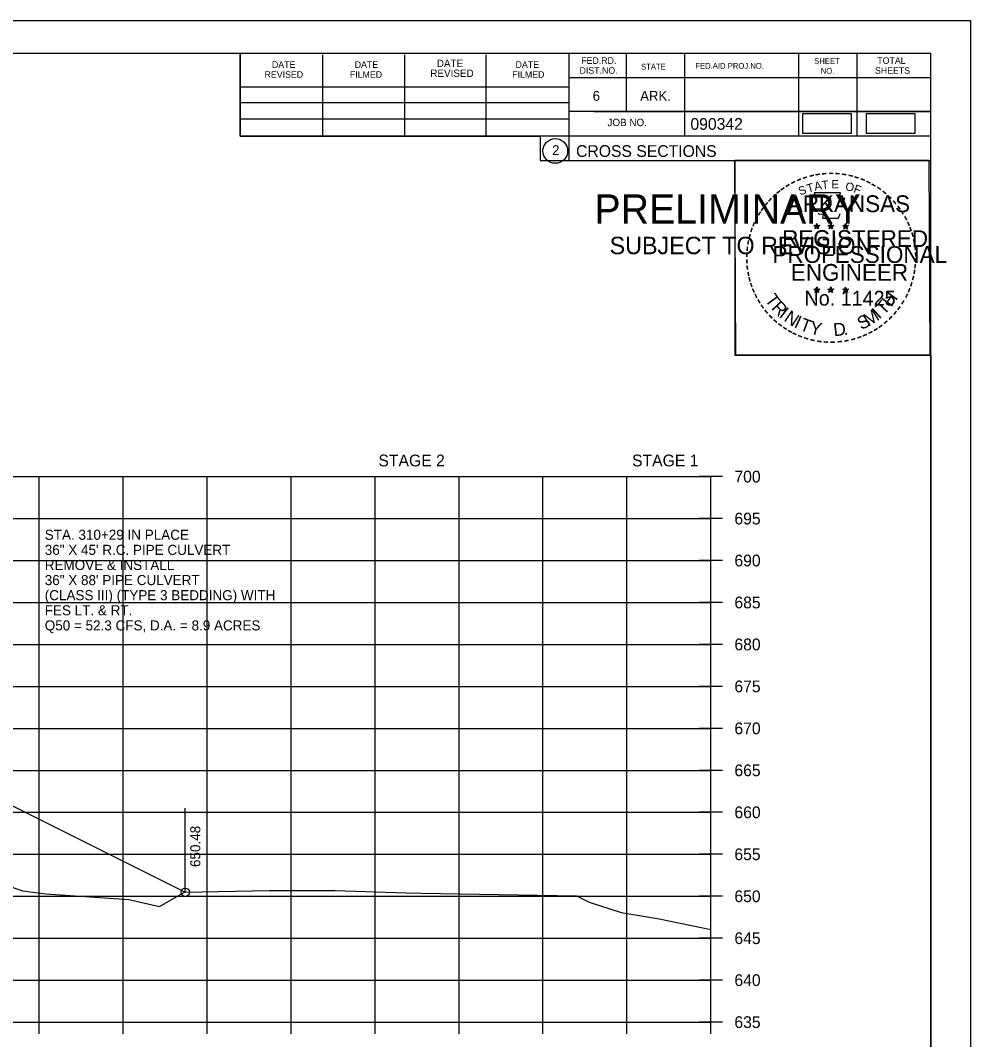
# Model space of a CAD drawing. Extents: x 1370515 to 1370849, y 383299 to 386073.
# Drawn here: x 1370735.6 to 1370848.7, y 384884.7 to 385006.1 of the extents above; entities that cross this region are included whole.
import ezdxf

# ---------------------------------------------------------------- set-up
doc = ezdxf.new("R2010")
doc.units = 0
for name, color, linetype in [('R_Axis', 7, 'Continuous'), ('R_Axis Annot', 7, 'Continuous'), ('R_Border', 7, 'Continuous'), ('R_Border PE', 7, 'Continuous'), ('R_Border Prem', 7, 'Continuous'), ('R_Detour', 7, 'Continuous'), ('R_Exist Surface', 7, 'Continuous'), ('R_Fin Surface', 7, 'Continuous'), ('R_Grid', 7, 'Continuous'), ('R_No Plot', 7, 'Continuous'), ('R_Water', 7, 'Continuous'), ('R_Xsect Elev', 7, 'Continuous')]:
    doc.layers.add(name, color=color, linetype=linetype)

msp = doc.modelspace()

# ---------------------------------------------------------------- linework, layer by layer
at = {"layer": 'R_Axis'}
for p, q in [((1370819.2, 384951.77), (1370816.4, 384951.77)), ((1370817.8, 384886.77), (1370817.8, 384951.77)), ((1370819.2, 384946.77), (1370816.4, 384946.77)), ((1370819.2, 384941.77), (1370816.4, 384941.77)), ((1370819.2, 384936.77), (1370816.4, 384936.77)), ((1370819.2, 384931.77), (1370816.4, 384931.77)), ((1370819.2, 384926.77), (1370816.4, 384926.77)), ((1370819.2, 384921.77), (1370816.4, 384921.77)), ((1370819.2, 384916.77), (1370816.4, 384916.77)), ((1370819.2, 384911.77), (1370816.4, 384911.77)), ((1370819.2, 384906.77), (1370816.4, 384906.77)), ((1370819.2, 384901.77), (1370816.4, 384901.77)), ((1370819.2, 384896.77), (1370816.4, 384896.77)), ((1370819.2, 384891.77), (1370816.4, 384891.77)), ((1370737.8, 384885.37), (1370737.8, 384888.17)), ((1370747.8, 384885.37), (1370747.8, 384888.17)), ((1370757.8, 384885.37), (1370757.8, 384888.17)), ((1370767.8, 384885.37), (1370767.8, 384888.17)), ((1370777.8, 384885.37), (1370777.8, 384888.17)), ((1370787.8, 384885.37), (1370787.8, 384888.17)), ((1370797.8, 384885.37), (1370797.8, 384888.17)), ((1370807.8, 384885.37), (1370807.8, 384888.17)), ((1370817.8, 384885.37), (1370817.8, 384888.17)), ((1370537.8, 384886.77), (1370817.8, 384886.77)), ((1370819.2, 384886.77), (1370816.4, 384886.77))]:
    msp.add_line(p, q, dxfattribs=at)
at = {"layer": 'R_Border'}
for p, q in [((1370527.8, 385002.23), (1370843.98, 385002.23)), ((1370761.72, 384992.35), (1370761.72, 385002.23)), ((1370771.58, 384992.35), (1370771.58, 385002.03)), ((1370781.34, 384992.35), (1370781.34, 385002.03)), ((1370791.02, 384992.35), (1370791.02, 385002.03)), ((1370800.88, 385002.23), (1370800.88, 384989.43)), ((1370807.72, 385002.23), (1370807.72, 384995.29)), ((1370814.66, 385002.23), (1370814.66, 384992.35)), ((1370828.24, 385002.23), (1370828.24, 384992.35)), ((1370835.18, 385002.23), (1370835.18, 384992.35)), ((1370843.98, 384796.77), (1370843.98, 385002.23)), ((1370843.98, 384999.29), (1370800.88, 384999.29)), ((1370843.98, 384999.31), (1370843.98, 384999.31)), ((1370761.72, 384998.21), (1370800.88, 384998.21)), ((1370761.72, 384996.35), (1370800.88, 384996.35)), ((1370843.98, 384995.29), (1370800.88, 384995.29)), ((1370803.84, 384995.29), (1370843.98, 384995.29)), ((1370761.72, 384992.35), (1370761.72, 384994.41)), ((1370761.72, 384994.41), (1370800.88, 384994.41)), ((1370843.98, 384992.35), (1370761.72, 384992.35)), ((1370800.88, 384989.43), (1370843.98, 384989.43))]:
    msp.add_line(p, q, dxfattribs=at)
msp.add_circle((1370799.27, 384990.57), 1.47, dxfattribs=at)
at = {"layer": 'R_Border PE'}
for p, q in [((1370830.42, 384981.94), (1370830.37, 384981.69)), ((1370830.42, 384981.58), (1370830.42, 384981.94)), ((1370830.42, 384981.94), (1370830.46, 384981.69)), ((1370832.09, 384981.94), (1370832.04, 384981.69)), ((1370832.09, 384981.58), (1370832.09, 384981.94)), ((1370832.09, 384981.94), (1370832.13, 384981.69)), ((1370833.85, 384981.93), (1370833.81, 384981.68)), ((1370833.85, 384981.57), (1370833.85, 384981.93)), ((1370833.85, 384981.93), (1370833.9, 384981.68)), ((1370830.07, 384981.69), (1370830.42, 384981.58)), ((1370830.07, 384981.69), (1370830.32, 384981.64)), ((1370830.07, 384981.69), (1370830.3, 384981.57)), ((1370830.2, 384981.28), (1370830.42, 384981.58)), ((1370830.2, 384981.28), (1370830.33, 384981.53)), ((1370830.2, 384981.28), (1370830.41, 384981.5)), ((1370830.63, 384981.28), (1370830.41, 384981.5)), ((1370830.76, 384981.69), (1370830.42, 384981.58)), ((1370830.63, 384981.28), (1370830.42, 384981.58)), ((1370830.76, 384981.69), (1370830.48, 384981.64)), ((1370830.63, 384981.28), (1370830.49, 384981.57)), ((1370830.76, 384981.69), (1370830.56, 384981.59)), ((1370831.74, 384981.69), (1370832.09, 384981.58)), ((1370831.74, 384981.69), (1370831.99, 384981.64)), ((1370831.74, 384981.69), (1370831.97, 384981.57)), ((1370831.87, 384981.28), (1370832.09, 384981.58)), ((1370831.87, 384981.28), (1370832, 384981.53)), ((1370831.87, 384981.28), (1370832.08, 384981.5)), ((1370832.3, 384981.28), (1370832.08, 384981.5)), ((1370832.43, 384981.69), (1370832.09, 384981.58)), ((1370832.3, 384981.28), (1370832.09, 384981.58)), ((1370832.43, 384981.69), (1370832.15, 384981.64)), ((1370832.3, 384981.28), (1370832.16, 384981.57)), ((1370832.43, 384981.69), (1370832.23, 384981.59)), ((1370833.5, 384981.68), (1370833.85, 384981.57)), ((1370833.5, 384981.68), (1370833.75, 384981.63)), ((1370833.5, 384981.68), (1370833.74, 384981.56)), ((1370833.63, 384981.27), (1370833.85, 384981.57)), ((1370833.63, 384981.27), (1370833.76, 384981.51)), ((1370833.63, 384981.27), (1370833.85, 384981.49)), ((1370834.2, 384981.68), (1370833.85, 384981.57)), ((1370834.06, 384981.27), (1370833.85, 384981.57)), ((1370834.06, 384981.27), (1370833.85, 384981.48)), ((1370834.2, 384981.68), (1370833.91, 384981.63)), ((1370834.06, 384981.27), (1370833.93, 384981.56)), ((1370834.2, 384981.68), (1370833.99, 384981.58)), ((1370830.06, 384974.12), (1370830.41, 384974.01)), ((1370830.06, 384974.12), (1370830.32, 384974.07)), ((1370830.06, 384974.12), (1370830.3, 384973.99)), ((1370830.2, 384973.71), (1370830.41, 384974.01)), ((1370830.2, 384973.71), (1370830.32, 384973.95)), ((1370830.2, 384973.71), (1370830.41, 384973.93)), ((1370830.41, 384974.37), (1370830.37, 384974.12)), ((1370830.41, 384974.01), (1370830.41, 384974.37)), ((1370830.41, 384974.37), (1370830.46, 384974.12)), ((1370830.76, 384974.12), (1370830.41, 384974.01)), ((1370830.62, 384973.71), (1370830.41, 384974.01)), ((1370830.62, 384973.71), (1370830.41, 384973.92)), ((1370830.76, 384974.12), (1370830.47, 384974.07)), ((1370830.62, 384973.71), (1370830.49, 384974)), ((1370830.76, 384974.12), (1370830.55, 384974.01)), ((1370831.73, 384974.12), (1370832.08, 384974.01)), ((1370831.73, 384974.12), (1370831.98, 384974.07)), ((1370831.73, 384974.12), (1370831.97, 384973.99)), ((1370831.86, 384973.71), (1370832.08, 384974.01)), ((1370831.86, 384973.71), (1370831.99, 384973.95)), ((1370831.86, 384973.71), (1370832.08, 384973.93)), ((1370832.08, 384974.37), (1370832.04, 384974.12)), ((1370832.08, 384974.01), (1370832.08, 384974.37)), ((1370832.08, 384974.37), (1370832.13, 384974.12)), ((1370832.43, 384974.12), (1370832.08, 384974.01)), ((1370832.29, 384973.71), (1370832.08, 384974.01)), ((1370832.29, 384973.71), (1370832.08, 384973.92)), ((1370832.43, 384974.12), (1370832.14, 384974.07)), ((1370832.29, 384973.71), (1370832.16, 384974)), ((1370832.43, 384974.12), (1370832.22, 384974.01)), ((1370833.5, 384974.11), (1370833.85, 384974)), ((1370833.5, 384974.11), (1370833.75, 384974.06)), ((1370833.5, 384974.11), (1370833.74, 384973.98)), ((1370833.63, 384973.7), (1370833.85, 384974)), ((1370833.63, 384973.7), (1370833.76, 384973.94)), ((1370833.63, 384973.7), (1370833.85, 384973.92)), ((1370833.85, 384974.36), (1370833.81, 384974.11)), ((1370833.85, 384974), (1370833.85, 384974.36)), ((1370833.85, 384974.36), (1370833.9, 384974.11)), ((1370834.19, 384974.11), (1370833.85, 384974)), ((1370834.06, 384973.7), (1370833.85, 384974)), ((1370834.06, 384973.7), (1370833.85, 384973.91)), ((1370834.19, 384974.11), (1370833.91, 384974.06)), ((1370834.06, 384973.7), (1370833.92, 384973.99)), ((1370834.19, 384974.11), (1370833.99, 384974))]:
    msp.add_line(p, q, dxfattribs=at)
for points in [[(1370830.11, 384985.57), (1370830.38, 384984.74)], [(1370833.62, 384984.65), (1370833.76, 384984.93), (1370833.08, 384984.91), (1370833.22, 384985.57), (1370830.11, 384985.57)], [(1370830.6, 384983.14), (1370830.6, 384983.06), (1370831.16, 384983.04), (1370831.11, 384982.57), (1370832.98, 384982.57), (1370833.18, 384983.1)], [(1370830.42, 384981.94), (1370830.63, 384981.28), (1370830.07, 384981.69), (1370830.76, 384981.69), (1370830.2, 384981.28), (1370830.42, 384981.94)], [(1370832.09, 384981.94), (1370832.3, 384981.28), (1370831.74, 384981.69), (1370832.43, 384981.69), (1370831.87, 384981.28), (1370832.09, 384981.94)], [(1370833.85, 384981.93), (1370834.06, 384981.27), (1370833.5, 384981.68), (1370834.2, 384981.68), (1370833.63, 384981.27), (1370833.85, 384981.93)], [(1370830.41, 384974.37), (1370830.62, 384973.71), (1370830.06, 384974.12), (1370830.76, 384974.12), (1370830.2, 384973.71), (1370830.41, 384974.37)], [(1370832.08, 384974.37), (1370832.29, 384973.71), (1370831.73, 384974.12), (1370832.43, 384974.12), (1370831.86, 384973.71), (1370832.08, 384974.37)], [(1370833.85, 384974.36), (1370834.06, 384973.7), (1370833.5, 384974.11), (1370834.19, 384974.11), (1370833.63, 384973.7), (1370833.85, 384974.36)]]:
    msp.add_lwpolyline(points, dxfattribs=at)
for centre, radius in [((1370830.41, 384981.58), 0.172), ((1370830.41, 384981.58), 0.145), ((1370830.41, 384981.58), 0.116), ((1370830.41, 384981.58), 0.0991), ((1370830.41, 384981.58), 0.0747), ((1370830.41, 384981.58), 0.0495), ((1370830.41, 384981.58), 0.0296), ((1370832.08, 384981.58), 0.172), ((1370832.08, 384981.58), 0.145), ((1370832.08, 384981.58), 0.116), ((1370832.08, 384981.58), 0.0991), ((1370832.08, 384981.58), 0.0747), ((1370832.08, 384981.58), 0.0495), ((1370832.08, 384981.58), 0.0296), ((1370833.85, 384981.57), 0.172), ((1370833.85, 384981.57), 0.145), ((1370833.85, 384981.57), 0.116), ((1370833.85, 384981.57), 0.0991), ((1370833.85, 384981.57), 0.0747), ((1370833.85, 384981.57), 0.0495), ((1370833.85, 384981.57), 0.0296), ((1370830.41, 384974.01), 0.172), ((1370830.41, 384974.01), 0.145), ((1370830.41, 384974.01), 0.116), ((1370830.41, 384974.01), 0.0991), ((1370830.41, 384974.01), 0.0747), ((1370830.41, 384974.01), 0.0495), ((1370830.41, 384974.01), 0.0296), ((1370832.08, 384974.01), 0.172), ((1370832.08, 384974.01), 0.145), ((1370832.08, 384974.01), 0.116), ((1370832.08, 384974.01), 0.0991), ((1370832.08, 384974.01), 0.0747), ((1370832.08, 384974.01), 0.0495), ((1370832.08, 384974.01), 0.0296), ((1370833.85, 384974), 0.172), ((1370833.85, 384974), 0.145), ((1370833.85, 384974), 0.116), ((1370833.85, 384974), 0.0991), ((1370833.85, 384974), 0.0747), ((1370833.85, 384974), 0.0495), ((1370833.85, 384974), 0.0296)]:
    msp.add_circle(centre, radius, dxfattribs=at)
at = {"layer": 'R_Detour'}
for points in [[(1370828.7, 384992.69), (1370834.53, 384992.69), (1370834.53, 384995), (1370828.7, 384995)], [(1370836.3, 384992.69), (1370842.14, 384992.69), (1370842.14, 384995), (1370836.3, 384995)]]:
    msp.add_lwpolyline(points, close=True, dxfattribs=at)
at = {"layer": 'R_Exist Surface'}
msp.add_lwpolyline([(1370734.44, 384902.89), (1370735.82, 384902.41), (1370738.57, 384902.04), (1370748.48, 384901.37), (1370752.12, 384900.55), (1370755.09, 384902.24), (1370755.18, 384902.25), (1370765.19, 384902.47), (1370773.06, 384902.46), (1370781.52, 384902.18), (1370783.3, 384902.14), (1370801.8, 384901.8), (1370803.3, 384901.06), (1370807.11, 384899.83), (1370811.64, 384899.06), (1370817.8, 384897.82)], dxfattribs=at)
at = {"layer": 'R_Fin Surface'}
msp.add_lwpolyline([(1370588.17, 384925.44), (1370626.49, 384923.33), (1370651.8, 384931.77), (1370657.8, 384933.27), (1370665.8, 384932.51), (1370677.8, 384931.36), (1370689.8, 384930.21), (1370697.8, 384929.45), (1370703.8, 384927.95), (1370708.72, 384925.49), (1370755.19, 384902.25)], dxfattribs=at)
at = {"layer": 'R_Grid'}
for p, q in [((1370537.8, 384951.77), (1370817.8, 384951.77)), ((1370737.8, 384886.77), (1370737.8, 384951.77)), ((1370747.8, 384886.77), (1370747.8, 384951.77)), ((1370757.8, 384886.77), (1370757.8, 384951.77)), ((1370767.8, 384886.77), (1370767.8, 384951.77)), ((1370777.8, 384886.77), (1370777.8, 384951.77)), ((1370787.8, 384886.77), (1370787.8, 384951.77)), ((1370797.8, 384886.77), (1370797.8, 384951.77)), ((1370807.8, 384886.77), (1370807.8, 384951.77)), ((1370817.8, 384886.77), (1370817.8, 384951.77)), ((1370537.8, 384946.77), (1370817.8, 384946.77)), ((1370537.8, 384941.77), (1370817.8, 384941.77)), ((1370537.8, 384936.77), (1370817.8, 384936.77)), ((1370537.8, 384931.77), (1370817.8, 384931.77)), ((1370537.8, 384926.77), (1370817.8, 384926.77)), ((1370537.8, 384921.77), (1370817.8, 384921.77)), ((1370537.8, 384916.77), (1370817.8, 384916.77)), ((1370537.8, 384911.77), (1370817.8, 384911.77)), ((1370537.8, 384906.77), (1370817.8, 384906.77)), ((1370537.8, 384901.77), (1370817.8, 384901.77)), ((1370537.8, 384896.77), (1370817.8, 384896.77)), ((1370537.8, 384891.77), (1370817.8, 384891.77)), ((1370537.8, 384886.77), (1370817.8, 384886.77))]:
    msp.add_line(p, q, dxfattribs=at)
at = {"layer": 'R_No Plot'}
for p, q in [((1370515.4, 385006.13), (1370848.73, 385006.13)), ((1370820.02, 384966.98), (1370820.02, 384966.98))]:
    msp.add_line(p, q, dxfattribs=at)
for points in [[(1370515.39, 385006.13), (1370848.73, 385006.13), (1370848.73, 384792.79), (1370515.39, 384792.79)], [(1370761.72, 385002.23), (1370761.72, 384992.35), (1370797.45, 384992.35), (1370797.45, 384989.43), (1370820.65, 384989.43), (1370820.65, 384966.22), (1370843.98, 384966.22), (1370843.98, 384796.77), (1370527.8, 384796.77), (1370527.8, 385002.23)], [(1370820.65, 384989.47), (1370843.75, 384989.47), (1370843.87, 384966.22), (1370820.77, 384966.22)]]:
    msp.add_lwpolyline(points, close=True, dxfattribs=at)
msp.add_circle((1370755.19, 384902.25), 0.5, dxfattribs=at)
at = {"layer": 'R_Xsect Elev'}
msp.add_line((1370755.19, 384902.25), (1370755.19, 384912.25), dxfattribs=at)

# ---------------------------------------------------------------- texts
at = {"layer": 'R_Axis Annot'}
for s, p in [('STAGE 2', (1370778.2, 384952.99)), ('STAGE 1', (1370808.41, 384952.99)), ('700', (1370820.6, 384951.07)), ('695', (1370820.6, 384946.07)), ('690', (1370820.6, 384941.07)), ('685', (1370820.6, 384936.07)), ('680', (1370820.6, 384931.07)), ('675', (1370820.6, 384926.07)), ('670', (1370820.6, 384921.07)), ('665', (1370820.6, 384916.07)), ('660', (1370820.6, 384911.07)), ('655', (1370820.6, 384906.07)), ('650', (1370820.6, 384901.07)), ('645', (1370820.6, 384896.07)), ('640', (1370820.6, 384891.07)), ('635', (1370820.6, 384886.07))]:
    msp.add_text(s, height=1.4, dxfattribs=at).set_placement(p)
at = {"layer": 'R_Border'}
for s, height, p in [('DATE', 0.879, (1370785.16, 385000.57)), ('FED.RD.', 0.782, (1370802.36, 385000.95)), ('SHEET', 0.684, (1370830.1, 385000.95)), ('TOTAL', 0.782, (1370837.62, 385000.95)), ('REVISED', 0.782, (1370764.64, 384999.29)), ('DATE', 0.782, (1370765.52, 385000.47)), ('FILMED', 0.782, (1370774.8, 384999.29)), ('DATE', 0.782, (1370775.38, 385000.47)), ('REVISED', 0.879, (1370784.38, 384999.39)), ('FILMED', 0.782, (1370794.14, 384999.29)), ('DATE', 0.782, (1370794.54, 385000.47)), ('DIST.NO.', 0.782, (1370802.16, 384999.77)), ('STATE', 0.684, (1370809.48, 385000.27)), ('FED.AID PROJ.NO.', 0.684, (1370815.94, 385000.37)), ('NO.', 0.684, (1370830.88, 384999.77)), ('SHEETS', 0.782, (1370837.34, 384999.77)), ('6', 1.17, (1370803.72, 384996.55)), ('ARK.', 1.172, (1370809.38, 384996.55)), ('JOB NO.', 0.879, (1370805.48, 384993.53)), ('090342', 1.4, (1370815.36, 384993.09)), ('2', 1.17, (1370798.89, 384990.08)), ('CROSS SECTIONS', 1.4, (1370801.74, 384989.86))]:
    msp.add_text(s, height=height, rotation=360, dxfattribs=at).set_placement(p)
at = {"layer": 'R_Border PE'}
for s, height, rotation, p in [('-', 1.6, 5.8968, (1370831.01, 384987.21)), ('-', 1.6, 0.1862, (1370831.78, 384987.28)), ('-', 1.6, 357.743, (1370832.51, 384987.27)), ('-', 1.6, 28.7918, (1370827.59, 384986.11)), ('-', 1.6, 24.3072, (1370828.22, 384986.43)), ('-', 1.6, 19.1761, (1370828.86, 384986.69)), ('T', 1, 16.4036, (1370829.38, 384985.58)), ('-', 1.6, 13.6301, (1370829.61, 384986.94)), ('A', 1, 11.2132, (1370830.2, 384985.83)), ('-', 1.6, 10.2193, (1370830.28, 384987.1)), ('T', 1, 6.0228, (1370831.05, 384985.99)), ('E', 1, 0.8323, (1370832.16, 384986.1)), ('-', 1.6, 352.1617, (1370833.25, 384987.21)), ('O', 1, 350.4515, (1370833.76, 384985.89)), ('-', 1.6, 347.2049, (1370833.97, 384987.1)), ('-', 1.6, 342.3362, (1370834.61, 384986.94)), ('-', 1.6, 337.8551, (1370835.34, 384986.72)), ('-', 1.6, 334.1211, (1370835.97, 384986.45)), ('-', 1.6, 329.6409, (1370836.55, 384986.16)), ('-', 1.6, 42.9622, (1370825.5, 384984.55)), ('-', 1.6, 38.9507, (1370825.94, 384984.97)), ('-', 1.6, 36.2317, (1370826.41, 384985.34)), ('-', 1.6, 34.0636, (1370826.99, 384985.74)), ('S', 1, 21.594, (1370828.46, 384985.25)), ('F', 1, 340.0707, (1370834.71, 384985.67)), ('-', 1.6, 325.8627, (1370837.19, 384985.8)), ('-', 1.6, 320.5297, (1370837.8, 384985.38)), ('-', 1.6, 50.6142, (1370824.65, 384983.58)), ('-', 1.6, 48.423, (1370825.06, 384984.07)), ('ARKANSAS', 2, 360, (1370826.96, 384983.28)), ('-', 1.6, 315.5786, (1370838.4, 384984.89)), ('-', 1.6, 309.8797, (1370838.97, 384984.34)), ('-', 1.6, 58.0706, (1370823.92, 384982.49)), ('-', 1.6, 54.2325, (1370824.24, 384983.02)), ('-', 1.6, 306.6522, (1370839.5, 384983.74)), ('-', 1.4, 303.6753, (1370839.98, 384983.17)), ('-', 1.6, 67.7743, (1370823.34, 384981.27)), ('-', 1.6, 62.8713, (1370823.6, 384981.88)), ('-', 1.6, 299.6684, (1370840.3, 384982.56)), ('-', 1.6, 294.6628, (1370840.63, 384981.95)), ('-', 1.6, 75.461, (1370822.93, 384979.92)), ('-', 1.6, 72.3945, (1370823.12, 384980.64)), ('REGISTERED', 2, 360, (1370826.28, 384979.13)), ('DWB', 0.01, 360, (1370830.4, 384981.57)), ('DWB', 0.01, 360, (1370832.07, 384981.57)), ('DWB', 0.01, 360, (1370833.84, 384981.56)), ('-', 1.6, 290.5728, (1370840.88, 384981.37)), ('-', 1.6, 285.1233, (1370841.12, 384980.79)), ('-', 1.6, 81.2013, (1370822.8, 384979.21)), ('-', 1.6, 280.5493, (1370841.32, 384980.05)), ('-', 1.6, 89.0622, (1370822.69, 384977.82)), ('-', 1.6, 85.1863, (1370822.72, 384978.52)), ('PROFESSIONAL', 2, 360, (1370825.13, 384977.23)), ('-', 1.6, 276.5962, (1370841.48, 384979.28)), ('-', 1.6, 274.3301, (1370841.54, 384978.56)), ('-', 1.6, 94.1959, (1370822.73, 384977.09)), ('ENGINEER', 2, 360, (1370827.32, 384975.1)), ('-', 1.6, 263.5172, (1370841.55, 384977.26)), ('-', 1.6, 269.9407, (1370841.57, 384977.93)), ('-', 1.6, 98.9479, (1370822.8, 384976.42)), ('-', 1.6, 101.7149, (1370822.94, 384975.69)), ('-', 1.6, 260.9953, (1370841.48, 384976.61)), ('-', 1.6, 105.4578, (1370823.1, 384975.1)), ('-', 1.6, 109.0874, (1370823.31, 384974.47)), ('-', 1.6, 252.8681, (1370841.19, 384975.21)), ('-', 1.6, 255.7626, (1370841.37, 384975.93)), ('-', 1.6, 114.0643, (1370823.57, 384973.87)), ('-', 1.6, 115.7288, (1370823.87, 384973.25)), ('T', 1.54, 306.0406, (1370824.17, 384972.84)), ('No. 11425', 1.757, 360, (1370828.95, 384972.15)), ('DWB', 0.01, 360, (1370830.4, 384974)), ('DWB', 0.01, 360, (1370832.07, 384974)), ('DWB', 0.01, 360, (1370833.83, 384973.99)), ('H', 1.54, 54.6088, (1370839.29, 384971.88)), ('-', 1.6, 244.6197, (1370840.71, 384973.91)), ('-', 1.6, 247.8887, (1370840.97, 384974.54)), ('-', 1.6, 120.4471, (1370824.23, 384972.67)), ('-', 1.6, 125.8934, (1370824.63, 384972.1)), ('R', 1.54, 314.005, (1370824.93, 384971.8)), ('T', 1.54, 46.6444, (1370838.4, 384970.94)), ('-', 1.6, 239.0712, (1370840.31, 384973.16)), ('-', 1.6, 130.7181, (1370825.09, 384971.55)), ('-', 1.6, 134.2238, (1370825.61, 384971.01)), ('I', 1.54, 321.9694, (1370825.83, 384970.86)), ('N', 1.54, 326.5002, (1370826.4, 384970.39)), ('I', 1.54, 335.3603, (1370827.61, 384969.61)), ('S', 1.54, 26.9312, (1370835.72, 384969.21)), ('M', 1.54, 32.6563, (1370836.56, 384969.61)), ('I', 1.54, 42.1136, (1370837.84, 384970.46)), ('-', 1.6, 225.7653, (1370839, 384971.37)), ('-', 1.6, 231.2538, (1370839.48, 384971.94)), ('-', 1.6, 233.8452, (1370839.91, 384972.5)), ('-', 1.6, 138.9338, (1370826.14, 384970.54)), ('-', 1.6, 144.6463, (1370826.69, 384970.14)), ('T', 1.54, 339.8912, (1370828.27, 384969.28)), ('Y', 1.54, 347.8556, (1370829.49, 384968.83)), ('D', 1.54, 6.3969, (1370832.47, 384968.48)), ('-', 1.6, 215.7363, (1370837.93, 384970.39)), ('-', 1.6, 221.0851, (1370838.48, 384970.87)), ('-', 1.6, 148.0898, (1370827.25, 384969.77)), ('-', 1.6, 151.5704, (1370827.83, 384969.44)), ('-', 1.6, 154.6002, (1370828.35, 384969.19)), ('-', 1.6, 158.5612, (1370828.98, 384968.94)), ('.', 1.54, 13.7642, (1370833.66, 384968.6)), ('-', 1.6, 200.7184, (1370835.6, 384969.07)), ('-', 1.6, 204.2516, (1370836.21, 384969.34)), ('-', 1.6, 207.3568, (1370836.84, 384969.66)), ('-', 1.6, 212.2491, (1370837.4, 384970.01)), ('-', 1.6, 162.7983, (1370829.67, 384968.73)), ('-', 1.6, 167.5555, (1370830.38, 384968.56)), ('-', 1.6, 173.1155, (1370831.15, 384968.45)), ('-', 1.6, 176.5183, (1370831.9, 384968.4)), ('-', 1.6, 181.5918, (1370832.64, 384968.42)), ('-', 1.6, 185.8167, (1370833.45, 384968.5)), ('-', 1.6, 191.2858, (1370834.19, 384968.63)), ('-', 1.6, 195.4743, (1370834.92, 384968.83))]:
    msp.add_text(s, height=height, rotation=rotation, dxfattribs=at).set_placement(p)
at = {"layer": 'R_Border Prem'}
for s, height, p in [('PRELIMINARY', 3.5, (1370803.93, 384981.9)), ('DWB', 0.01, (1370804.68, 384983.75)), ('SUBJECT TO REVISION', 2.0751, (1370805.74, 384978.27))]:
    msp.add_text(s, height=height, rotation=360, dxfattribs=at).set_placement(p)
at = {"layer": 'R_No Plot'}
for p in [(1370755.14, 384902.2), (1370801.76, 384901.75), (1370752.08, 384900.5), (1370807.07, 384899.78)]:
    msp.add_text('+', height=0.1, dxfattribs=at).set_placement(p)
at = {"layer": 'R_Water'}
for s, p in [('STA. 310+29 IN PLACE', (1370738.46, 384944.24)), ('36" X 45\' R.C. PIPE CULVERT', (1370738.46, 384942.44)), ('REMOVE & INSTALL', (1370738.46, 384940.64)), ('36" X 88\' PIPE CULVERT', (1370738.46, 384938.84)), ('(CLASS III) (TYPE 3 BEDDING) WITH', (1370738.46, 384937.04)), ('FES LT. & RT.', (1370738.46, 384935.24)), ('Q50 = 52.3 CFS, D.A. = 8.9 ACRES', (1370738.46, 384933.44))]:
    msp.add_text(s, height=1.2, dxfattribs=at).set_placement(p)
at = {"layer": 'R_Xsect Elev'}
msp.add_text('650.48', height=1.2, rotation=90, dxfattribs=at).set_placement((1370756.99, 384905.25))

doc.saveas('drawing.dxf')
